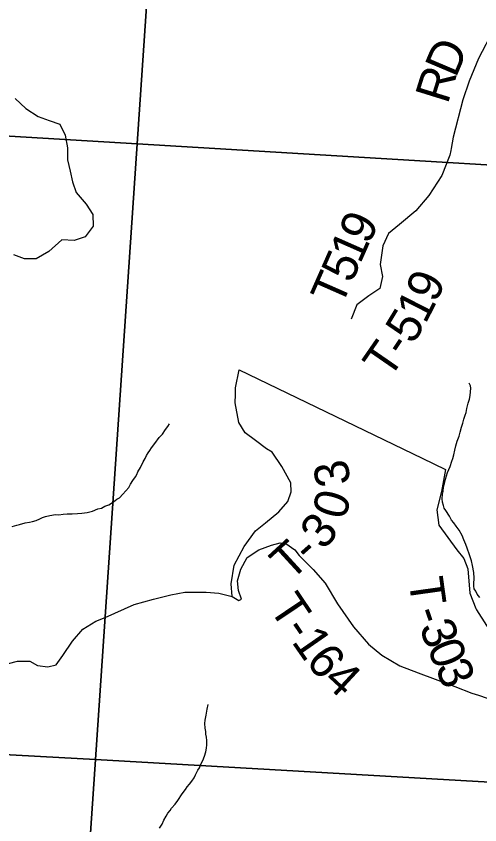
# Model space of a CAD drawing. Extents: x 0 to 34, y 0 to 22.
# Drawn here: x 7.778 to 8.54, y 17.764 to 19.094 of the extents above; entities that cross this region are included whole.
import ezdxf

# ---------------------------------------------------------------- set-up
doc = ezdxf.new("R2010")
doc.units = 0
for name, color, linetype in [('GM_X_Minor_River', 7, 'Continuous'), ('GM_X_Section', 7, 'Continuous'), ('GM_X_Township_Road', 7, 'Continuous'), ('GM_X_Township_Road_Text', 7, 'Continuous'), ('GM_X_Township_ROW', 7, 'Continuous')]:
    doc.layers.add(name, color=color, linetype=linetype)

msp = doc.modelspace()

# ---------------------------------------------------------------- linework, layer by layer
at = {"layer": 'GM_X_Minor_River'}
for points in [[(7.7759, 18.9585), (7.7933, 18.9418), (7.8137, 18.9289), (7.8318, 18.9221), (7.8492, 18.916), (7.8583, 18.8978), (7.862, 18.8773), (7.862, 18.8576), (7.8665, 18.8386), (7.8703, 18.8212), (7.8763, 18.8037), (7.8929, 18.7847), (7.9035, 18.7673), (7.9042, 18.7483), (7.8913, 18.7309), (7.8731, 18.7248), (7.8527, 18.7256), (7.8315, 18.7066), (7.8103, 18.6945), (7.7913, 18.6945), (7.7739, 18.7014)], [(8.5402, 18.1379), (8.5357, 18.1432), (8.5332, 18.1479), (8.5306, 18.1517), (8.5299, 18.1563), (8.53, 18.1601), (8.5305, 18.1695), (8.5299, 18.1787), (8.5279, 18.1901), (8.5261, 18.1977), (8.5232, 18.208), (8.5189, 18.2187), (8.5171, 18.2248), (8.5138, 18.2325), (8.5109, 18.2394), (8.5062, 18.2482), (8.501, 18.2551), (8.4973, 18.2605), (8.4936, 18.2647), (8.4899, 18.2713), (8.484, 18.2805), (8.4814, 18.2843), (8.48, 18.2889), (8.4786, 18.2942), (8.4783, 18.2999), (8.4788, 18.3075), (8.4796, 18.3117), (8.4805, 18.3196), (8.4817, 18.3249), (8.4838, 18.3321), (8.4866, 18.3431), (8.4913, 18.3529), (8.4941, 18.3616), (8.4957, 18.3665), (8.497, 18.3725), (8.499, 18.3801), (8.5006, 18.3869), (8.5027, 18.3945), (8.5059, 18.4031), (8.5079, 18.4096), (8.5099, 18.4175), (8.5119, 18.4243), (8.5139, 18.4311), (8.5156, 18.4375), (8.5175, 18.4417), (8.5188, 18.4485), (8.5208, 18.4572), (8.5228, 18.4636), (8.5241, 18.4697), (8.5249, 18.4761), (8.5254, 18.4818), (8.5247, 18.486), (8.5225, 18.4902)], [(8.013, 18.4009), (8.0181, 18.4061), (8.0231, 18.414), (8.027, 18.4189), (8.0297, 18.423)], [(7.7711, 18.2542), (7.7787, 18.2568), (7.7833, 18.2578), (7.7924, 18.2603), (7.7996, 18.2613), (7.8046, 18.2628), (7.8103, 18.2642), (7.8164, 18.2671), (7.8209, 18.269), (7.8259, 18.2708), (7.8331, 18.2726), (7.8422, 18.2739), (7.8479, 18.2738), (7.8551, 18.2748), (7.8612, 18.2751), (7.8657, 18.275), (7.8699, 18.2753), (7.8783, 18.2756), (7.8858, 18.2762), (7.8946, 18.2776), (7.9033, 18.2797), (7.9117, 18.2834), (7.9178, 18.2848), (7.9236, 18.2881), (7.9297, 18.2903), (7.9377, 18.2951), (7.9431, 18.2992), (7.9473, 18.3014), (7.9531, 18.3077), (7.9581, 18.313), (7.9627, 18.3186), (7.9658, 18.3238), (7.9694, 18.3299), (7.9736, 18.3359), (7.976, 18.34), (7.9779, 18.3441), (7.9819, 18.3517), (7.9862, 18.3607), (7.9897, 18.3664), (7.9917, 18.3713), (7.9944, 18.3754), (7.9975, 18.3795), (7.9999, 18.3837), (8.0057, 18.3911), (8.013, 18.4009)], [(8.0131, 17.7586), (8.0174, 17.765), (8.0205, 17.7714), (8.024, 17.7782), (8.0272, 17.783), (8.031, 17.7872), (8.033, 17.7913), (8.0388, 17.7977), (8.0434, 17.804), (8.0504, 17.8146), (8.0562, 17.8221), (8.059, 17.8262), (8.0628, 17.8307), (8.0663, 17.8356), (8.0702, 17.8412), (8.0726, 17.8461), (8.0765, 17.8536), (8.0788, 17.8578), (8.0812, 17.8638), (8.0844, 17.8698), (8.0871, 17.877), (8.0892, 17.8838), (8.0904, 17.8899), (8.0909, 17.8956), (8.091, 17.9024), (8.0907, 17.9081), (8.0897, 17.9127), (8.0894, 17.9172), (8.0883, 17.923), (8.0877, 17.9306), (8.0882, 17.9359), (8.0898, 17.9442), (8.0915, 17.9541), (8.0932, 17.9616)]]:
    msp.add_lwpolyline(points, dxfattribs=at)
at = {"layer": 'GM_X_Section'}
for points in [[(6.9795, 19.9566), (8.0453, 19.8934), (7.9764, 18.8836), (6.9173, 18.9472)], [(8.0453, 19.8934), (9.1186, 19.8297), (9.0999, 19.5424), (9.0522, 18.819), (7.9764, 18.8836)], [(6.9173, 18.9472), (7.9764, 18.8836), (7.9078, 17.8715), (6.8533, 17.9287)], [(7.9764, 18.8836), (9.0522, 18.819), (9.0316, 18.5064), (8.9857, 17.8095), (7.9078, 17.8715)], [(6.8533, 17.9287), (7.9078, 17.8715), (7.8396, 16.8632), (6.7904, 16.9223)], [(7.9078, 17.8715), (8.9857, 17.8095), (8.9637, 17.4779), (8.9185, 16.8056), (7.8396, 16.8632)]]:
    msp.add_lwpolyline(points, close=True, dxfattribs=at)
at = {"layer": 'GM_X_Township_Road'}
for points in [[(8.5713, 19.0895), (8.5624, 19.0712), (8.538, 19.0241), (8.5227, 18.987), (8.512, 18.9559), (8.4961, 18.8946), (8.4928, 18.876)], [(8.4928, 18.876), (8.4922, 18.8726), (8.4909, 18.865), (8.4777, 18.8316), (8.4562, 18.7985), (8.4346, 18.7734), (8.4078, 18.751), (8.39, 18.7362), (8.3806, 18.7157), (8.3761, 18.6853), (8.3799, 18.6656), (8.3754, 18.6458), (8.3576, 18.634), (8.338, 18.6188), (8.3285, 18.5953)], [(8.1325, 18.1395), (8.1309, 18.16), (8.1358, 18.1911), (8.1524, 18.2215), (8.1709, 18.2474), (8.1876, 18.2603), (8.2095, 18.2786), (8.2242, 18.2957), (8.2299, 18.3116), (8.2291, 18.3264), (8.2143, 18.3533), (8.1987, 18.3765), (8.1892, 18.3821), (8.1709, 18.3957), (8.1542, 18.4082), (8.1436, 18.4257), (8.1378, 18.4579), (8.138, 18.4715)], [(8.4452, 18.3667), (8.4834, 18.3483), (8.477, 18.3122), (8.4691, 18.2818), (8.4726, 18.2564), (8.5019, 18.2159), (8.5137, 18.2019), (8.5202, 18.1848), (8.5233, 18.1446), (8.5332, 18.1196), (8.5347, 18.1172)], [(7.7651, 18.029), (7.7799, 18.0332), (7.8, 18.0329), (7.8125, 18.0261), (7.8296, 18.0238), (7.8436, 18.0269), (7.8545, 18.0421), (7.8704, 18.0657), (7.8874, 18.0855), (7.9086, 18.0988), (7.9237, 18.1049), (7.9714, 18.1263), (8.0033, 18.1347), (8.0321, 18.1423), (8.0552, 18.1462), (8.09, 18.1466), (8.1109, 18.1448), (8.1325, 18.1395), (8.1435, 18.1327), (8.1481, 18.135), (8.1431, 18.149), (8.1415, 18.165), (8.1472, 18.184), (8.1574, 18.2037), (8.1767, 18.2159), (8.1975, 18.2239), (8.2115, 18.2274), (8.221, 18.2266), (8.2358, 18.216), (8.243, 18.2069), (8.2662, 18.1838), (8.2856, 18.1611), (8.3058, 18.1274), (8.332, 18.0895), (8.3567, 18.0611), (8.3791, 18.0429), (8.4087, 18.0255), (8.4387, 18.0139), (8.499, 17.9912), (8.5271, 17.9803), (8.5379, 17.9768)], [(8.5347, 18.1172), (8.5637, 18.0718), (8.5702, 18.0453), (8.5736, 18.0198), (8.5843, 18.0051), (8.6139, 17.9865), (8.6811, 17.9613), (8.7175, 17.939)], [(8.5379, 17.9768), (8.5518, 17.9724), (8.5745, 17.9732), (8.5916, 17.9671), (8.6121, 17.9588), (8.628, 17.9532), (8.6523, 17.9464), (8.6902, 17.9416), (8.7107, 17.9389), (8.7175, 17.939), (8.7225, 17.9374), (8.7418, 17.9284), (8.7592, 17.9167), (8.7703, 17.9079), (8.7802, 17.8901), (8.7931, 17.878), (8.8173, 17.8647)]]:
    msp.add_lwpolyline(points, dxfattribs=at)
at = {"layer": 'GM_X_Township_ROW'}
msp.add_lwpolyline([(8.138, 18.4715), (8.1381, 18.4822), (8.1441, 18.5118), (8.4452, 18.3667)], dxfattribs=at)

# ---------------------------------------------------------------- texts
at = {"layer": 'GM_X_Township_Road_Text'}
for s, rotation, p in [('D', 67.0188, (8.5003, 18.9908)), ('R', 72.7224, (8.487, 18.9476)), ('9', 64.4712, (8.3572, 18.7165)), ('1', 66.1548, (8.3432, 18.6849)), ('5', 66.2338, (8.3291, 18.6529)), ('T', 66.2292, (8.312, 18.614)), ('9', 66.216, (8.4679, 18.6205)), ('1', 62.8549, (8.4504, 18.586)), ('5', 58.8068, (8.4301, 18.5523)), ('T', 55.373, (8.391, 18.4948)), ('-', 56.2977, (8.4157, 18.5306)), ('3', 101.1951, (8.3286, 18.3262)), ('0', 74.0864, (8.3178, 18.2635)), ('3', 50.2171, (8.2834, 18.214)), ('T', 42.5689, (8.2282, 18.1631)), ('-', 41.3842, (8.2593, 18.1917)), ('T', 277.9496, (8.4226, 18.1673)), ('T', 303.8443, (8.1921, 18.1204)), ('-', 288.6748, (8.4311, 18.1139)), ('3', 291.3763, (8.4396, 18.0891)), ('1', 304.8157, (8.2294, 18.0649)), ('-', 304.0449, (8.2159, 18.0849)), ('6', 309.0831, (8.2522, 18.0324)), ('0', 291.9386, (8.4526, 18.0559)), ('3', 292.5491, (8.4659, 18.0228)), ('4', 317.1842, (8.2802, 17.9989))]:
    msp.add_text(s, height=0.0568, rotation=rotation, dxfattribs=at).set_placement(p)

doc.saveas('drawing.dxf')
